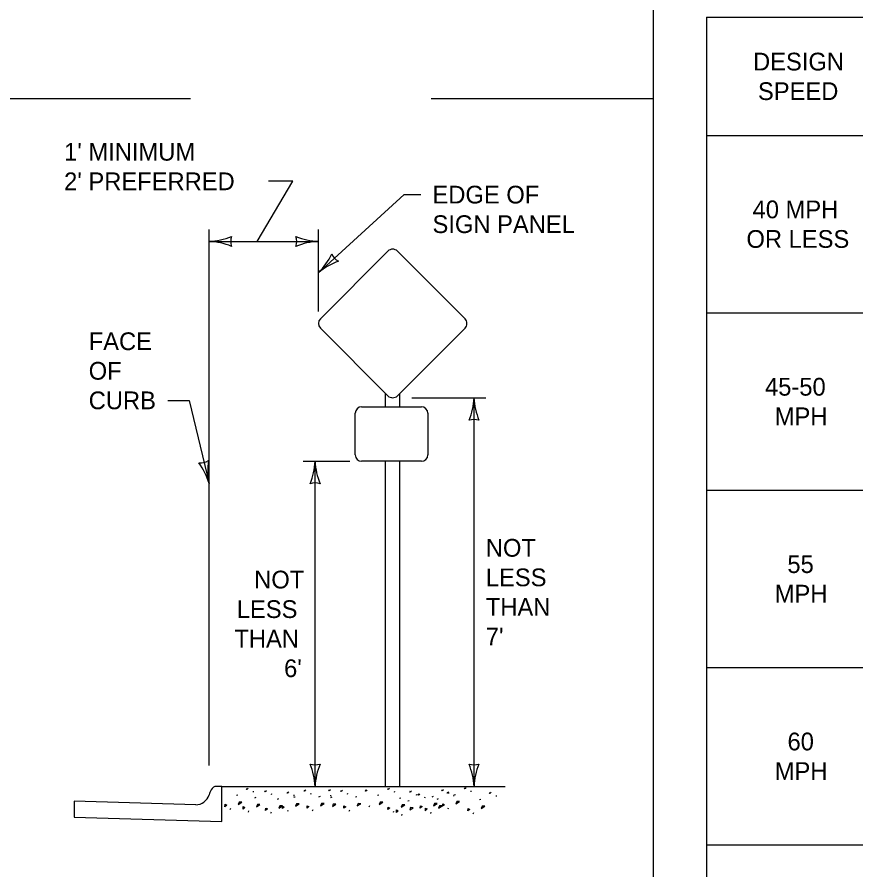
# Model space of a CAD drawing. Extents: x 49991.4 to 50021, y 49987.6 to 50011.4.
# Drawn here: x 50005.916 to 50008.753, y 49990.684 to 49993.569 of the extents above; entities that cross this region are included whole.
import ezdxf

# ---------------------------------------------------------------- set-up
doc = ezdxf.new("R2010")
doc.units = 0
for name, color, linetype in [('Level 1', 7, 'Continuous'), ('Level 2', 7, 'Continuous'), ('Level 3', 7, 'Continuous')]:
    doc.layers.add(name, color=color, linetype=linetype)

msp = doc.modelspace()

# ---------------------------------------------------------------- linework, layer by layer
at = {"layer": 'Level 1'}
for p, q in [((50006.9416, 49992.5484), (50007.1702, 49992.7772)), ((50007.202, 49992.7772), (50007.4309, 49992.5484)), ((50007.1702, 49992.2877), (50006.9416, 49992.5166)), ((50007.4309, 49992.5166), (50007.202, 49992.2877)), ((50007.1618, 49992.2506), (50007.1618, 49992.2961)), ((50007.2104, 49992.2506), (50007.2104, 49992.2961)), ((50007.081, 49992.2506), (50007.2836, 49992.2506)), ((50007.0595, 49992.0878), (50007.0595, 49992.2291)), ((50007.3051, 49992.2291), (50007.3051, 49992.0878)), ((50007.2836, 49992.0663), (50007.081, 49992.0663)), ((50007.1618, 49990.9661), (50007.1618, 49992.0663)), ((50007.2104, 49990.9661), (50007.2104, 49992.0663)), ((50006.6082, 49990.9661), (50006.5913, 49990.9661)), ((50006.6082, 49990.9661), (50007.5665, 49990.9661)), ((50006.6082, 49990.8476), (50006.6082, 49990.9661)), ((50006.6622, 49990.9368), (50006.6576, 49990.9352)), ((50006.6922, 49990.9563), (50006.6942, 49990.961)), ((50006.6966, 49990.9574), (50006.6922, 49990.9563)), ((50006.6942, 49990.961), (50006.6966, 49990.9574)), ((50006.7151, 49990.9467), (50006.7156, 49990.9503)), ((50006.7538, 49990.9483), (50006.7558, 49990.953)), ((50006.7583, 49990.9494), (50006.7538, 49990.9483)), ((50006.7558, 49990.953), (50006.7583, 49990.9494)), ((50006.7767, 49990.9387), (50006.7772, 49990.9423)), ((50006.8297, 49990.9436), (50006.8318, 49990.9483)), ((50006.8342, 49990.9446), (50006.8297, 49990.9436)), ((50006.8318, 49990.9483), (50006.8342, 49990.9446)), ((50006.8526, 49990.934), (50006.8531, 49990.9376)), ((50006.8866, 49990.95), (50006.8886, 49990.9547)), ((50006.8911, 49990.9511), (50006.8866, 49990.95)), ((50006.8886, 49990.9547), (50006.8911, 49990.9511)), ((50006.9095, 49990.9404), (50006.91, 49990.944)), ((50006.9704, 49990.9516), (50006.9724, 49990.9563)), ((50006.9749, 49990.9527), (50006.9704, 49990.9516)), ((50006.9724, 49990.9563), (50006.9749, 49990.9527)), ((50006.9768, 49990.9333), (50006.9773, 49990.9369)), ((50007.0108, 49990.9493), (50007.0128, 49990.954)), ((50007.0153, 49990.9504), (50007.0108, 49990.9493)), ((50007.0128, 49990.954), (50007.0153, 49990.9504)), ((50007.0337, 49990.9397), (50007.0342, 49990.9433)), ((50007.0946, 49990.9509), (50007.0966, 49990.9556)), ((50007.0991, 49990.952), (50007.0946, 49990.9509)), ((50007.0966, 49990.9556), (50007.0991, 49990.952)), ((50007.1396, 49990.9368), (50007.135, 49990.9352)), ((50007.1695, 49990.9563), (50007.1716, 49990.961)), ((50007.174, 49990.9574), (50007.1695, 49990.9563)), ((50007.1716, 49990.961), (50007.174, 49990.9574)), ((50007.1924, 49990.9467), (50007.1929, 49990.9503)), ((50007.2439, 49990.9467), (50007.2459, 49990.9514)), ((50007.2483, 49990.9478), (50007.2439, 49990.9467)), ((50007.2459, 49990.9514), (50007.2483, 49990.9478)), ((50007.2668, 49990.9371), (50007.2673, 49990.9408)), ((50007.2722, 49990.9372), (50007.2743, 49990.942)), ((50007.2767, 49990.9383), (50007.2722, 49990.9372)), ((50007.2743, 49990.942), (50007.2767, 49990.9383)), ((50007.3529, 49990.9516), (50007.355, 49990.9563)), ((50007.3574, 49990.9527), (50007.3529, 49990.9516)), ((50007.355, 49990.9563), (50007.3574, 49990.9527)), ((50007.3702, 49990.9436), (50007.3723, 49990.9483)), ((50007.3747, 49990.9446), (50007.3702, 49990.9436)), ((50007.3723, 49990.9483), (50007.3747, 49990.9446)), ((50007.3758, 49990.942), (50007.3763, 49990.9456)), ((50007.3932, 49990.934), (50007.3936, 49990.9376)), ((50007.3987, 49990.9383), (50007.3941, 49990.9368)), ((50007.4287, 49990.9579), (50007.4308, 49990.9626)), ((50007.4332, 49990.959), (50007.4287, 49990.9579)), ((50007.4308, 49990.9626), (50007.4332, 49990.959)), ((50007.4516, 49990.9483), (50007.4521, 49990.9519)), ((50007.5141, 49990.942), (50007.5161, 49990.9467)), ((50007.5186, 49990.9431), (50007.5141, 49990.942)), ((50007.5161, 49990.9467), (50007.5186, 49990.9431)), ((50007.537, 49990.9324), (50007.5375, 49990.936)), ((50006.5199, 49990.9044), (50006.1083, 49990.9168)), ((50006.1083, 49990.9168), (50006.1083, 49990.8627)), ((50006.6668, 49990.9137), (50006.6635, 49990.9058)), ((50006.6635, 49990.9058), (50006.6757, 49990.9135)), ((50006.6757, 49990.9135), (50006.6668, 49990.9137)), ((50006.7238, 49990.9288), (50006.7192, 49990.9272)), ((50006.7997, 49990.924), (50006.7951, 49990.9225)), ((50006.8566, 49990.9305), (50006.852, 49990.9289)), ((50006.8612, 49990.9074), (50006.8579, 49990.8995)), ((50006.8579, 49990.8995), (50006.8701, 49990.9072)), ((50006.8701, 49990.9072), (50006.8612, 49990.9074)), ((50006.9404, 49990.932), (50006.9358, 49990.9305)), ((50006.945, 49990.909), (50006.9418, 49990.9011)), ((50006.9418, 49990.9011), (50006.9539, 49990.9087)), ((50006.9539, 49990.9087), (50006.945, 49990.909)), ((50006.9808, 49990.9298), (50006.9762, 49990.9282)), ((50007.0646, 49990.9313), (50007.06, 49990.9298)), ((50007.0692, 49990.9083), (50007.066, 49990.9004)), ((50007.066, 49990.9004), (50007.0781, 49990.908)), ((50007.0781, 49990.908), (50007.0692, 49990.9083)), ((50007.1442, 49990.9137), (50007.1409, 49990.9058)), ((50007.1409, 49990.9058), (50007.153, 49990.9135)), ((50007.153, 49990.9135), (50007.1442, 49990.9137)), ((50007.2139, 49990.9272), (50007.2093, 49990.9256)), ((50007.2423, 49990.9177), (50007.2377, 49990.9161)), ((50007.2952, 49990.9277), (50007.2956, 49990.9313)), ((50007.3229, 49990.932), (50007.3183, 49990.9305)), ((50007.3275, 49990.909), (50007.3243, 49990.9011)), ((50007.3243, 49990.9011), (50007.3364, 49990.9087)), ((50007.3364, 49990.9087), (50007.3275, 49990.909)), ((50007.3403, 49990.924), (50007.3357, 49990.9225)), ((50007.3551, 49990.8994), (50007.3556, 49990.9077)), ((50007.3556, 49990.9077), (50007.3614, 49990.9044)), ((50007.4033, 49990.9153), (50007.4001, 49990.9074)), ((50007.4001, 49990.9074), (50007.4122, 49990.9151)), ((50007.4122, 49990.9151), (50007.4033, 49990.9153)), ((50007.4841, 49990.9225), (50007.4795, 49990.9209)), ((50006.6185, 49990.8978), (50006.619, 49990.9061)), ((50006.6248, 49990.9028), (50006.6185, 49990.8978)), ((50006.619, 49990.9061), (50006.6248, 49990.9028)), ((50006.6373, 49990.8916), (50006.6358, 49990.8874)), ((50006.6802, 49990.8898), (50006.6806, 49990.8981)), ((50006.6865, 49990.8948), (50006.6802, 49990.8898)), ((50006.6806, 49990.8981), (50006.6865, 49990.8948)), ((50006.6989, 49990.8836), (50006.6974, 49990.8794)), ((50006.7284, 49990.9057), (50006.7251, 49990.8978)), ((50006.7251, 49990.8978), (50006.7373, 49990.9055)), ((50006.7373, 49990.9055), (50006.7284, 49990.9057)), ((50006.7561, 49990.8851), (50006.7566, 49990.8933)), ((50006.7624, 49990.8901), (50006.7561, 49990.8851)), ((50006.7566, 49990.8933), (50006.7624, 49990.8901)), ((50006.7749, 49990.8789), (50006.7733, 49990.8747)), ((50006.8043, 49990.901), (50006.8011, 49990.8931)), ((50006.8011, 49990.8931), (50006.8132, 49990.9007)), ((50006.8132, 49990.9007), (50006.8043, 49990.901)), ((50006.813, 49990.8915), (50006.8134, 49990.8998)), ((50006.8193, 49990.8965), (50006.813, 49990.8915)), ((50006.8134, 49990.8998), (50006.8193, 49990.8965)), ((50006.8318, 49990.8853), (50006.8302, 49990.8811)), ((50006.8968, 49990.8931), (50006.8972, 49990.9013)), ((50006.9031, 49990.8981), (50006.8968, 49990.8931)), ((50006.8972, 49990.9013), (50006.9031, 49990.8981)), ((50006.9156, 49990.8869), (50006.914, 49990.8827)), ((50006.9854, 49990.9067), (50006.9821, 49990.8988)), ((50006.9821, 49990.8988), (50006.9943, 49990.9065)), ((50006.9943, 49990.9065), (50006.9854, 49990.9067)), ((50007.021, 49990.8924), (50007.0214, 49990.9006)), ((50007.0273, 49990.8974), (50007.021, 49990.8924)), ((50007.0214, 49990.9006), (50007.0273, 49990.8974)), ((50007.0398, 49990.8862), (50007.0382, 49990.882)), ((50007.1076, 49990.9008), (50007.106, 49990.8966)), ((50007.1702, 49990.8883), (50007.1707, 49990.8965)), ((50007.1766, 49990.8932), (50007.1702, 49990.8883)), ((50007.1707, 49990.8965), (50007.1766, 49990.8932)), ((50007.189, 49990.8821), (50007.1875, 49990.8778)), ((50007.1986, 49990.8788), (50007.1991, 49990.887)), ((50007.2049, 49990.8838), (50007.1986, 49990.8788)), ((50007.1991, 49990.887), (50007.2049, 49990.8838)), ((50007.2185, 49990.9041), (50007.2152, 49990.8963)), ((50007.2152, 49990.8963), (50007.2274, 49990.9039)), ((50007.2274, 49990.9039), (50007.2185, 49990.9041)), ((50007.2469, 49990.8947), (50007.2436, 49990.8868)), ((50007.2436, 49990.8868), (50007.2557, 49990.8944)), ((50007.2557, 49990.8944), (50007.2469, 49990.8947)), ((50007.2793, 49990.8931), (50007.2798, 49990.9013)), ((50007.2856, 49990.8981), (50007.2793, 49990.8931)), ((50007.2798, 49990.9013), (50007.2856, 49990.8981)), ((50007.2981, 49990.8869), (50007.2965, 49990.8827)), ((50007.2966, 49990.8851), (50007.2971, 49990.8933)), ((50007.3029, 49990.8901), (50007.2966, 49990.8851)), ((50007.2971, 49990.8933), (50007.3029, 49990.8901)), ((50007.3154, 49990.8789), (50007.3138, 49990.8747)), ((50007.3449, 49990.901), (50007.3416, 49990.8931)), ((50007.3416, 49990.8931), (50007.3537, 49990.9007)), ((50007.3537, 49990.9007), (50007.3449, 49990.901)), ((50007.3614, 49990.9044), (50007.3551, 49990.8994)), ((50007.3739, 49990.8932), (50007.3723, 49990.889)), ((50007.4405, 49990.8835), (50007.4409, 49990.8918)), ((50007.4468, 49990.8885), (50007.4405, 49990.8835)), ((50007.4409, 49990.8918), (50007.4468, 49990.8885)), ((50007.4887, 49990.8994), (50007.4855, 49990.8915)), ((50007.4855, 49990.8915), (50007.4976, 49990.8992)), ((50007.4976, 49990.8992), (50007.4887, 49990.8994)), ((50006.1083, 49990.8627), (50006.6082, 49990.8476)), ((50007.2174, 49990.8726), (50007.2158, 49990.8684)), ((50007.4593, 49990.8773), (50007.4577, 49990.8731))]:
    msp.add_line(p, q, dxfattribs=at)
for centre, radius, start, end in [((50007.1861, 49992.7613), 0.0225, 45.011, 135.022), ((50006.9575, 49992.5325), 0.0225, 135.022, 224.967), ((50007.4149, 49992.5325), 0.0225, 315, 45.011), ((50007.1861, 49992.3036), 0.0225, 224.967, 315), ((50007.081, 49992.2291), 0.0215, 90, 180), ((50007.2836, 49992.2291), 0.0215, 0, 90), ((50007.081, 49992.0878), 0.0215, 180, 270), ((50007.2836, 49992.0878), 0.0215, 270, 0), ((50006.5896, 49990.9468), 0.0194, 85.2356, 156.6889), ((50006.5195, 49990.9521), 0.0477, 270.4937, 342.4535), ((50006.616, 49990.9268), 0.0521, 147.9305, 167.8949)]:
    msp.add_arc(centre, radius, start, end, dxfattribs=at)
at = {"layer": 'Level 2'}
for p, q in [((50008.2479, 49993.5684), (50008.2479, 49990.1684)), ((50008.2479, 49993.5684), (50013.0279, 49993.5684)), ((50008.2479, 49993.1684), (50013.0279, 49993.1684)), ((50008.2479, 49992.5684), (50013.0279, 49992.5684)), ((50008.2479, 49991.9684), (50013.0279, 49991.9684)), ((50008.2479, 49991.3684), (50013.0279, 49991.3684)), ((50008.2479, 49990.7684), (50013.0279, 49990.7684))]:
    msp.add_line(p, q, dxfattribs=at)
at = {"layer": 'Level 3'}
for p, q in [((50008.0668, 49994.0732), (50008.0668, 49987.7988)), ((50005.0025, 49993.2934), (50006.5025, 49993.2934)), ((50007.3168, 49993.2934), (50008.0668, 49993.2934)), ((50006.7274, 49992.8101), (50006.8479, 49993.0134)), ((50006.8479, 49993.0134), (50006.7663, 49993.0134)), ((50006.935, 49992.7042), (50007.2254, 49992.9684)), ((50007.2254, 49992.9684), (50007.2808, 49992.9684)), ((50006.565, 49991.0377), (50006.565, 49992.8501)), ((50006.935, 49992.5725), (50006.935, 49992.8501)), ((50006.565, 49992.8101), (50006.935, 49992.8101)), ((50006.4262, 49992.2724), (50006.4982, 49992.2724)), ((50006.4982, 49992.2724), (50006.565, 49991.9909)), ((50007.2504, 49992.2811), (50007.5012, 49992.2811)), ((50007.4612, 49990.9661), (50007.4612, 49992.2811)), ((50006.8838, 49992.0663), (50007.041, 49992.0663)), ((50006.9238, 49990.9661), (50006.9238, 49992.0663))]:
    msp.add_line(p, q, dxfattribs=at)
for centre, radius, start, end in [((50006.5535, 49993.0428), 0.233, 272.8273, 292.0772), ((50006.6932, 49992.8101), 0.0548, 162.1388, 197.8612), ((50006.9442, 49993.0322), 0.2223, 247.456, 267.6395), ((50006.8068, 49992.8101), 0.0548, 342.1388, 17.8612), ((50006.5559, 49992.588), 0.2223, 67.456, 87.6395), ((50006.9465, 49992.5774), 0.233, 92.8273, 112.0772), ((50006.7699, 49992.8686), 0.233, 315.1279, 334.3778), ((50007.0298, 49992.7905), 0.0548, 204.4394, 240.1618), ((50007.0777, 49992.5337), 0.2223, 109.7566, 129.9401), ((50007.2391, 49992.2903), 0.2223, 337.456, 357.6395), ((50007.6939, 49992.2926), 0.233, 182.8273, 202.0772), ((50007.4612, 49992.1529), 0.0548, 72.1388, 107.8612), ((50006.5346, 49992.1155), 0.0548, 265.8498, 301.5721), ((50006.783, 49992.0347), 0.2223, 171.1669, 191.3505), ((50006.7017, 49992.0755), 0.2223, 337.456, 357.6395), ((50007.1565, 49992.0778), 0.233, 182.8273, 202.0772), ((50006.3417, 49991.9246), 0.233, 16.5382, 35.7881), ((50006.9238, 49991.9381), 0.0548, 72.1388, 107.8612), ((50006.9238, 49991.0943), 0.0548, 252.1388, 287.8612), ((50006.6911, 49990.9546), 0.233, 2.8273, 22.0772), ((50007.1459, 49990.9569), 0.2223, 157.456, 177.6395), ((50007.4612, 49991.0943), 0.0548, 252.1388, 287.8612), ((50007.2285, 49990.9546), 0.233, 2.8273, 22.0772), ((50007.6833, 49990.9569), 0.2223, 157.456, 177.6395)]:
    msp.add_arc(centre, radius, start, end, dxfattribs=at)

# ---------------------------------------------------------------- texts
at = {"layer": 'Level 2'}
for s, p in [('DESIGN', (50008.405, 49993.3884)), ('SPEED', (50008.4216, 49993.2884)), ("1' MINIMUM", (50006.0748, 49993.0834)), ("2' PREFERRED", (50006.0748, 49992.9834)), ('EDGE OF', (50007.3208, 49992.9384)), ('40 MPH', (50008.4035, 49992.8884)), ('SIGN PANEL', (50007.3208, 49992.8384)), ('OR LESS', (50008.3827, 49992.7884)), ('FACE', (50006.158, 49992.4424)), ('OF', (50006.158, 49992.3424)), ('45-50', (50008.4455, 49992.2884)), ('CURB', (50006.158, 49992.2424)), ('MPH', (50008.4784, 49992.1884)), ('NOT', (50007.5012, 49991.7436)), ('55', (50008.5211, 49991.6884)), ('NOT', (50006.7177, 49991.6362)), ('LESS', (50007.5012, 49991.6436)), ('MPH', (50008.4784, 49991.5884)), ('THAN', (50007.5012, 49991.5436)), ('LESS', (50006.6589, 49991.5362)), ('THAN', (50006.6507, 49991.4362)), ("7'", (50007.5012, 49991.4436)), ("6'", (50006.8188, 49991.3362)), ('60', (50008.5216, 49991.0884)), ('MPH', (50008.4784, 49990.9884))]:
    msp.add_text(s, height=0.06, dxfattribs=at).set_placement(p)

doc.saveas('drawing.dxf')
